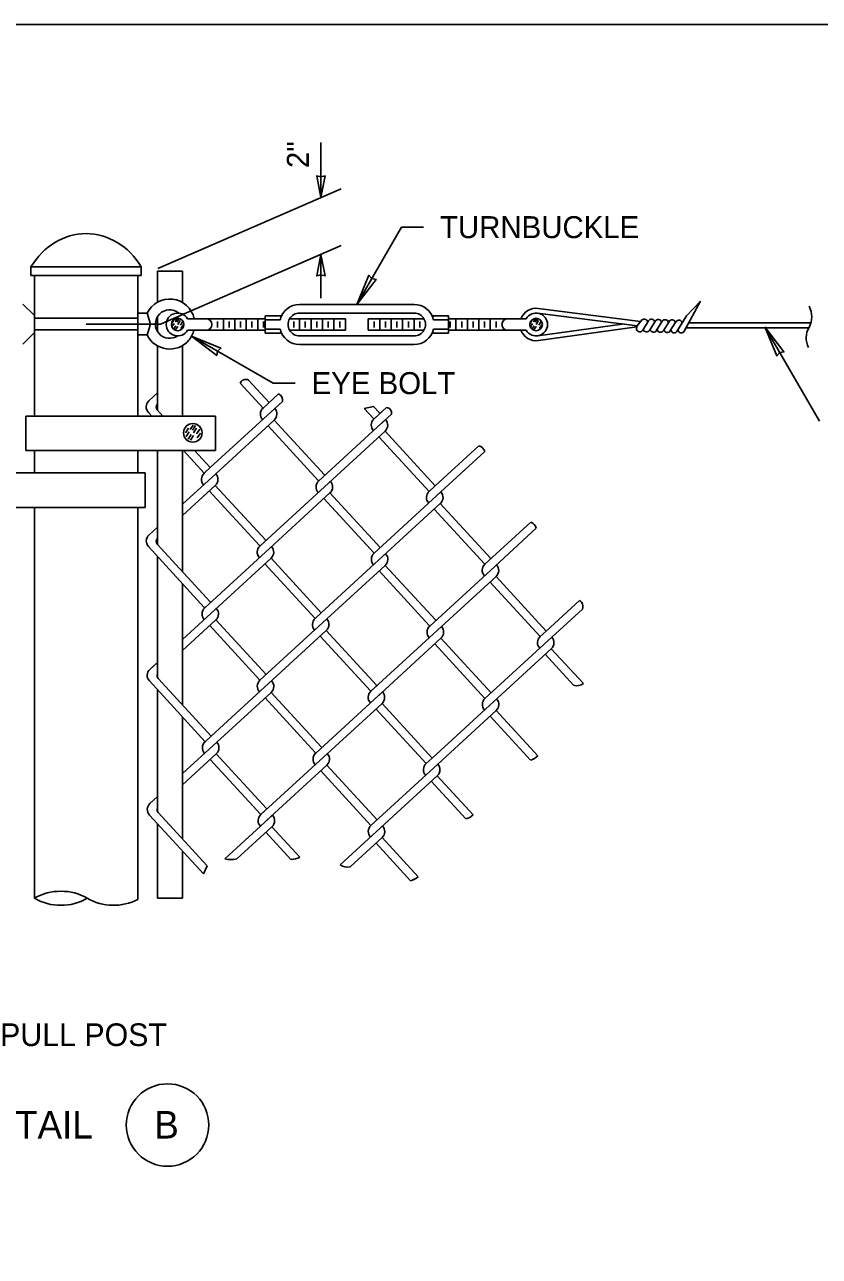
# Model space of a CAD drawing. Extents: x 99862 to 104211, y 98939 to 105076.
# Drawn here: x 101919 to 102497, y 104179 to 105076 of the extents above; entities that cross this region are included whole.
import ezdxf

# ---------------------------------------------------------------- set-up
doc = ezdxf.new("R2010")
doc.units = 0
for name, color, linetype in [('Level 1', 7, 'Continuous'), ('Level 15', 7, 'Continuous'), ('Level 2', 7, 'Continuous'), ('Level 20', 7, 'Continuous'), ('Level 4', 7, 'Continuous'), ('Level 7', 7, 'Continuous'), ('Level 9', 7, 'Continuous')]:
    doc.layers.add(name, color=color, linetype=linetype)

msp = doc.modelspace()

# ---------------------------------------------------------------- linework, layer by layer
at = {"layer": 'Level 1'}
msp.add_lwpolyline([(99862, 102999.5), (103151, 102999.5), (103151, 105075.5), (99862, 105075.5)], close=True, dxfattribs=at)
at = {"layer": 'Level 15'}
for p, q in [((102134.53, 104949.58), (102134.53, 104989.71)), ((102015.79, 104897.93), (102149.21, 104955.96)), ((102134.53, 104949.58), (102134.53, 104949.58)), ((102160.66, 104871.75), (102193.16, 104928.04)), ((102193.16, 104928.04), (102209.16, 104928.04)), ((102134.54, 104908.22), (102134.54, 104876.22)), ((102457.47, 104855.52), (102497.22, 104786.68)), ((102040.49, 104848.67), (102099.74, 104814.46)), ((102099.74, 104814.46), (102115.74, 104814.46))]:
    msp.add_line(p, q, dxfattribs=at)
for points in [[(102134.53, 104949.58), (102137.62, 104965.31), (102134.53, 104964.58), (102131.45, 104965.31)], [(102134.54, 104908.22), (102137.62, 104892.49), (102134.54, 104893.22), (102131.45, 104892.49)], [(102160.66, 104871.75), (102174.66, 104890.03), (102171.55, 104890.61), (102169.49, 104893.01)], [(102457.47, 104855.52), (102466.3, 104834.25), (102468.36, 104836.66), (102471.47, 104837.24)], [(102040.49, 104848.67), (102061.76, 104839.84), (102059.35, 104837.78), (102058.77, 104834.67)]]:
    msp.add_lwpolyline(points, close=True, dxfattribs=at)
msp.add_lwpolyline([(101963.72, 104857.47), (102017.83, 104857.47), (102149.21, 104914.6)], dxfattribs=at)
at = {"layer": 'Level 2'}
for p, q in [((101917.63, 104872.08), (101926.05, 104863.66)), ((102119.01, 104871.75), (102202.32, 104871.75)), ((102398.97, 104852.3), (102410.82, 104874.17)), ((102400.6, 104863.41), (102410.82, 104874.17)), ((102008.04, 104865.29), (102010.45, 104857.48)), ((102094.01, 104863.42), (102094.01, 104850.92)), ((102105.83, 104863.42), (102094.01, 104863.42)), ((102119.01, 104865.5), (102202.32, 104865.5)), ((102215.49, 104863.42), (102227.31, 104863.42)), ((102227.31, 104863.42), (102227.31, 104850.92)), ((102292.19, 104865.43), (102364.74, 104856.08)), ((102292.64, 104868.91), (102367.01, 104859.31)), ((102393.57, 104852.15), (102400.6, 104863.41)), ((101926.05, 104861.65), (101926.05, 104853.31)), ((101926.05, 104861.65), (102001.39, 104861.65)), ((101926.05, 104857.48), (101926.05, 104853.31)), ((102008.04, 104849.67), (102010.45, 104857.48)), ((102025.77, 104857.64), (102027.29, 104859.98)), ((102026.12, 104855.36), (102027.8, 104857.94)), ((102027.3, 104853.73), (102028.91, 104856.22)), ((102028.42, 104859.21), (102030.07, 104861.75)), ((102028.55, 104852.95), (102030.34, 104855.71)), ((102029.74, 104858.9), (102031.49, 104861.6)), ((102030.33, 104857.17), (102032.15, 104859.97)), ((102032.28, 104856.57), (102034.1, 104859.37)), ((102032.69, 104854.23), (102034.51, 104857.03)), ((102051.06, 104861.34), (102037.55, 104861.34)), ((102094.01, 104861.34), (102051.06, 104861.34)), ((102059.4, 104859.25), (102059.4, 104855.09)), ((102063.56, 104861.34), (102063.56, 104853.01)), ((102067.73, 104859.25), (102067.73, 104855.09)), ((102071.89, 104861.34), (102071.89, 104853.01)), ((102076.06, 104859.25), (102076.06, 104855.09)), ((102080.22, 104861.34), (102080.22, 104853.01)), ((102084.39, 104859.25), (102084.39, 104855.09)), ((102088.55, 104861.34), (102088.55, 104853.01)), ((102092.72, 104859.25), (102092.72, 104855.09)), ((102111.83, 104861.34), (102152.35, 104861.34)), ((102114.86, 104859.25), (102114.86, 104855.09)), ((102119.03, 104861.34), (102119.03, 104853.01)), ((102123.19, 104859.25), (102123.19, 104855.09)), ((102127.36, 104861.34), (102127.36, 104853.01)), ((102131.52, 104859.25), (102131.52, 104855.09)), ((102135.69, 104861.34), (102135.69, 104853.01)), ((102139.85, 104859.25), (102139.85, 104855.09)), ((102144.02, 104861.34), (102144.02, 104853.01)), ((102148.19, 104859.25), (102148.19, 104855.09)), ((102152.35, 104861.34), (102152.35, 104853.01)), ((102169.01, 104861.34), (102169.01, 104853.01)), ((102209.53, 104861.34), (102169.01, 104861.34)), ((102173.18, 104859.25), (102173.18, 104855.09)), ((102177.34, 104861.34), (102177.34, 104853.01)), ((102181.51, 104859.25), (102181.51, 104855.09)), ((102185.68, 104861.34), (102185.68, 104853.01)), ((102189.84, 104859.25), (102189.84, 104855.09)), ((102194.01, 104861.34), (102194.01, 104853.01)), ((102198.17, 104859.25), (102198.17, 104855.09)), ((102202.34, 104861.34), (102202.34, 104853.01)), ((102206.5, 104859.25), (102206.5, 104855.09)), ((102227.31, 104861.34), (102270.4, 104861.34)), ((102228.64, 104859.25), (102228.64, 104855.09)), ((102232.81, 104861.34), (102232.81, 104853.01)), ((102236.98, 104859.25), (102236.98, 104855.09)), ((102241.14, 104861.34), (102241.14, 104853.01)), ((102245.31, 104859.25), (102245.31, 104855.09)), ((102249.47, 104861.34), (102249.47, 104853.01)), ((102253.64, 104859.25), (102253.64, 104855.09)), ((102257.8, 104861.34), (102257.8, 104853.01)), ((102261.97, 104859.25), (102261.97, 104855.09)), ((102270.4, 104861.34), (102283.91, 104861.34)), ((102286.57, 104857.64), (102288.09, 104859.98)), ((102286.92, 104855.36), (102288.6, 104857.94)), ((102288.1, 104853.73), (102289.71, 104856.22)), ((102289.22, 104859.21), (102290.86, 104861.75)), ((102289.34, 104852.95), (102291.13, 104855.71)), ((102290.54, 104858.9), (102292.29, 104861.6)), ((102291.13, 104857.17), (102292.94, 104859.97)), ((102292.28, 104848.92), (102353.69, 104857.5)), ((102292.77, 104845.45), (102364.3, 104855.45)), ((102293.08, 104856.57), (102294.9, 104859.37)), ((102293.48, 104854.23), (102295.3, 104857.03)), ((102364.74, 104856.08), (102367.54, 104859.82)), ((102368.66, 104853), (102372.86, 104859.8)), ((102373.61, 104852.78), (102377.93, 104859.74)), ((102378.53, 104852.54), (102382.93, 104859.52)), ((102383.48, 104852.32), (102388.15, 104859.65)), ((102388.51, 104852.22), (102392.91, 104859.17)), ((102400.33, 104854.82), (102489.54, 104854.82)), ((102402.23, 104858.32), (102491.09, 104858.32)), ((101917.63, 104842.88), (101926.05, 104851.3)), ((101926.05, 104853.31), (102001.39, 104853.31)), ((102051.06, 104853.01), (102037.55, 104853.01)), ((102094.01, 104853.01), (102051.06, 104853.01)), ((102105.83, 104850.92), (102094.01, 104850.92)), ((102111.83, 104853.01), (102152.35, 104853.01)), ((102119, 104848.84), (102202.38, 104848.84)), ((102209.53, 104853.01), (102169.01, 104853.01)), ((102215.49, 104850.92), (102227.31, 104850.92)), ((102227.31, 104853.01), (102270.4, 104853.01)), ((102270.4, 104853.01), (102283.91, 104853.01)), ((102119, 104842.59), (102202.4, 104842.59))]:
    msp.add_line(p, q, dxfattribs=at)
for points in [[(101926.05, 104861.65), (101926.05, 104863.66)], [(102001.39, 104862.69), (102001.39, 104865.29), (102008.04, 104865.29)], [(102104.83, 104860.58), (102094.01, 104860.58)], [(102104.83, 104853.76), (102094.01, 104853.76)], [(102216.49, 104860.58), (102227.31, 104860.58)], [(102216.49, 104853.76), (102227.31, 104853.76)], [(101926.05, 104853.31), (101926.05, 104851.3)], [(102001.39, 104852.28), (102001.39, 104849.67), (102008.04, 104849.67)]]:
    msp.add_lwpolyline(points, dxfattribs=at)
for centre, radius in [((102030.33, 104857.17), 4.58), ((102291.13, 104857.17), 4.58), ((102041.31, 104778.25), 6.76)]:
    msp.add_circle(centre, radius, dxfattribs=at)
for centre, radius, start, end in [((102024.5, 104857.48), 18.22, 12.20835, 154.62307), ((102119, 104857.17), 14.58, 89.9981, 166.47525), ((102202.32, 104857.17), 14.58, 13.52807, 90.0019), ((102024.5, 104857.48), 10.41, 49.96946, 221.94815), ((102030.33, 104857.17), 8.33, 30, 330), ((102119, 104857.17), 8.33, 89.99821, 210), ((102202.32, 104857.17), 8.33, 329.99866, 90.00179), ((102291.13, 104857.17), 11.83, 82.64945, 159.385), ((102291.13, 104857.17), 8.33, 210, 150), ((102476.4, 104862.76), 15.35, 330, 30), ((102051.06, 104857.17), 4.17, 270, 90), ((102119, 104857.17), 14.58, 193.52475, 270), ((102202.32, 104857.17), 14.58, 270, 346.47623), ((102270.4, 104857.17), 4.17, 90, 270), ((102366.57, 104854.38), 2.5, 137.27331, 330.15706), ((102369.74, 104858.63), 2.5, 3.58666, 151.53493), ((102371.57, 104854.23), 2.5, 191.22024, 331.82535), ((102374.99, 104858.48), 2.5, 11.16264, 148.28981), ((102376.57, 104854.09), 2.5, 191.16264, 333.88098), ((102380, 104858.33), 2.5, 10.08945, 150.54633), ((102385.06, 104858.18), 2.5, 10.9904, 147.78546), ((102390.06, 104858.03), 2.5, 11.61323, 155.14251), ((102395.03, 104857.83), 2.5, 13.01144, 147.67573), ((102502.99, 104847.41), 15.35, 150, 206.99342), ((102024.5, 104857.48), 18.22, 205.37693, 319.9883), ((102024.5, 104857.48), 10.41, 221.94815, 303.90844), ((102024.5, 104857.48), 18.22, 319.9883, 345.77824), ((102119, 104857.17), 8.33, 210, 270), ((102202.32, 104857.17), 8.33, 270, 329.99866), ((102291.13, 104857.17), 11.83, 200.615, 277.95607), ((102381.57, 104853.94), 2.5, 191.03065, 335.14251), ((102386.57, 104853.79), 2.5, 190.91097, 334.35076), ((102391.56, 104853.64), 2.5, 190.98978, 332.61253), ((102396.77, 104853.49), 2.5, 184.71631, 331.55502)]:
    msp.add_arc(centre, radius, start, end, dxfattribs=at)
at = {"layer": 'Level 4'}
for p, q in [((102075.88, 104814.37), (102092.41, 104796.35)), ((102081.94, 104816.64), (102096.83, 104800.41)), ((102015.61, 104807.3), (102009.35, 104801.55)), ((102106.56, 104801.2), (102053.98, 104752.93)), ((102103.76, 104806.77), (102092.41, 104796.35)), ((102008.99, 104793.08), (102011.42, 104790.43)), ((102015.44, 104794.92), (102019.56, 104790.43)), ((102172.84, 104797.47), (102166.01, 104796.03)), ((102166.01, 104796.03), (102172.77, 104788.67)), ((102172.84, 104797.47), (102177.19, 104792.73)), ((102182.37, 104796.8), (102173.11, 104788.3)), ((102177.53, 104792.36), (102173.11, 104788.3)), ((102185.85, 104791.85), (102177.16, 104783.88)), ((102177.19, 104792.73), (102177.53, 104792.36)), ((102100.53, 104787.51), (102058.04, 104748.51)), ((102092.05, 104787.88), (102092.05, 104787.88)), ((102096.11, 104783.46), (102132.63, 104743.68)), ((102100.53, 104787.51), (102137.05, 104747.73)), ((102181.59, 104787.94), (102132.96, 104743.31)), ((102172.77, 104788.67), (102173.11, 104788.3)), ((102181.22, 104779.46), (102090.11, 104695.83)), ((102172.74, 104779.82), (102172.74, 104779.82)), ((102176.8, 104775.4), (102213.32, 104735.62)), ((102181.22, 104779.46), (102217.74, 104739.68)), ((102034.44, 104765.35), (102049.56, 104748.88)), ((102042.58, 104765.35), (102053.98, 104752.93)), ((102249.53, 104768.86), (102217.74, 104739.68)), ((102253.91, 104764.73), (102221.8, 104735.26)), ((102058.04, 104748.51), (102033.8, 104726.26)), ((102053.98, 104752.93), (102049.56, 104748.87)), ((102137.05, 104747.73), (102137.38, 104747.36)), ((102057.68, 104740.03), (102033.8, 104718.11)), ((102049.2, 104740.4), (102049.2, 104740.4)), ((102057.68, 104740.03), (102094.19, 104700.25)), ((102132.63, 104743.68), (102132.96, 104743.31)), ((102217.74, 104739.68), (102213.32, 104735.62)), ((102053.26, 104735.98), (102089.77, 104696.2)), ((102141.08, 104734.47), (102094.17, 104691.41)), ((102132.6, 104734.83), (102132.6, 104734.83)), ((102136.66, 104730.41), (102173.17, 104690.63)), ((102141.08, 104734.47), (102177.59, 104694.69)), ((102221.8, 104735.26), (102173.17, 104690.63)), ((102221.43, 104726.78), (102134.74, 104647.21)), ((102212.96, 104727.14), (102212.96, 104727.14)), ((102217.01, 104722.72), (102253.53, 104682.94)), ((102221.43, 104726.78), (102257.95, 104687)), ((102287.31, 104713.28), (102253.87, 104682.57)), ((102015.61, 104709.57), (102009.42, 104703.88)), ((102291.27, 104708.76), (102257.92, 104678.15)), ((102009.05, 104695.4), (102049.63, 104651.2)), ((102015.5, 104697.25), (102054.05, 104655.26)), ((102089.77, 104696.2), (102090.11, 104695.83)), ((102094.19, 104700.25), (102094.53, 104699.88)), ((102094.53, 104699.88), (102094.53, 104699.88)), ((102098.23, 104686.99), (102033.8, 104627.85)), ((102094.17, 104691.41), (102049.97, 104650.83)), ((102089.75, 104687.35), (102089.75, 104687.35)), ((102098.23, 104686.99), (102134.74, 104647.21)), ((102257.95, 104687), (102258.29, 104686.63)), ((102258.29, 104686.63), (102258.29, 104686.63)), ((102093.81, 104682.93), (102130.32, 104643.15)), ((102181.29, 104681.79), (102138.8, 104642.79)), ((102172.81, 104682.15), (102172.81, 104682.15)), ((102176.87, 104677.73), (102213.39, 104637.95)), ((102181.29, 104681.79), (102217.81, 104642.01)), ((102257.92, 104678.15), (102213.72, 104637.58)), ((102253.53, 104682.94), (102253.87, 104682.57)), ((102261.98, 104673.73), (102170.87, 104590.1)), ((102253.5, 104674.1), (102253.5, 104674.1)), ((102257.56, 104669.68), (102294.08, 104629.9)), ((102261.98, 104673.73), (102298.5, 104633.95)), ((102049.63, 104651.2), (102049.97, 104650.83)), ((102054.05, 104655.26), (102054.39, 104654.89)), ((102322.62, 104656.1), (102298.5, 104633.95)), ((102324.76, 104649.92), (102302.56, 104629.53)), ((102058.08, 104641.99), (102033.8, 104619.7)), ((102049.6, 104642.36), (102049.6, 104642.36)), ((102058.08, 104641.99), (102094.6, 104602.21)), ((102138.8, 104642.79), (102090.18, 104598.15)), ((102134.74, 104647.21), (102130.32, 104643.15)), ((102217.81, 104642.01), (102218.14, 104641.64)), ((102053.66, 104637.94), (102090.18, 104598.15)), ((102138.44, 104634.31), (102054.69, 104557.44)), ((102129.96, 104634.67), (102129.96, 104634.67)), ((102134.02, 104630.25), (102170.53, 104590.47)), ((102138.44, 104634.31), (102174.95, 104594.53)), ((102213.39, 104637.95), (102213.72, 104637.58)), ((102302.56, 104629.53), (102253.93, 104584.9)), ((102298.5, 104633.95), (102294.08, 104629.9)), ((102221.84, 104628.74), (102174.93, 104585.68)), ((102213.36, 104629.1), (102213.36, 104629.1)), ((102302.19, 104621.06), (102215.5, 104541.48)), ((102217.42, 104624.68), (102253.93, 104584.9)), ((102221.84, 104628.74), (102258.35, 104588.96)), ((102293.72, 104621.42), (102293.72, 104621.42)), ((102302.19, 104621.06), (102325.52, 104595.64)), ((102297.77, 104617), (102318.4, 104594.52)), ((102015.61, 104611.15), (102010.06, 104606.06)), ((102014.48, 104610.12), (102010.06, 104606.06)), ((102009.7, 104597.58), (102050.27, 104553.38)), ((102016.15, 104599.43), (102054.69, 104557.44)), ((102175.29, 104594.16), (102170.87, 104590.1)), ((102174.95, 104594.53), (102175.29, 104594.16)), ((102098.29, 104589.31), (102058.75, 104553.02)), ((102089.81, 104589.68), (102089.81, 104589.68)), ((102093.87, 104585.26), (102130.39, 104545.48)), ((102098.29, 104589.31), (102134.81, 104549.53)), ((102179.35, 104589.74), (102130.73, 104545.11)), ((102170.53, 104590.47), (102170.87, 104590.1)), ((102178.99, 104581.26), (102090.82, 104500.33)), ((102170.51, 104581.62), (102170.51, 104581.62)), ((102174.57, 104577.2), (102211.08, 104537.42)), ((102178.99, 104581.26), (102215.5, 104541.48)), ((102262.05, 104576.06), (102219.56, 104537.06)), ((102253.57, 104576.42), (102253.57, 104576.42)), ((102262.05, 104576.06), (102292.29, 104543.11)), ((102257.63, 104572), (102287.16, 104539.83)), ((102058.75, 104553.02), (102033.8, 104530.11)), ((102054.69, 104557.44), (102050.27, 104553.38)), ((102134.81, 104549.53), (102135.15, 104549.16)), ((102058.39, 104544.54), (102033.8, 104521.97)), ((102049.91, 104544.9), (102049.91, 104544.9)), ((102053.97, 104540.48), (102090.48, 104500.7)), ((102058.39, 104544.54), (102094.9, 104504.76)), ((102130.39, 104545.48), (102130.73, 104545.11)), ((102215.5, 104541.48), (102211.08, 104537.42)), ((102138.84, 104536.27), (102094.88, 104495.91)), ((102130.36, 104536.63), (102130.36, 104536.63)), ((102134.42, 104532.21), (102170.94, 104492.43)), ((102138.84, 104536.27), (102175.36, 104496.49)), ((102219.56, 104537.06), (102170.94, 104492.43)), ((102219.2, 104528.58), (102148.45, 104463.65)), ((102210.72, 104528.94), (102210.72, 104528.94)), ((102214.78, 104524.52), (102239.89, 104497.17)), ((102219.2, 104528.58), (102245.42, 104500.02)), ((102015.61, 104513.42), (102010.13, 104508.39)), ((102095.24, 104504.39), (102090.82, 104500.33)), ((102094.9, 104504.76), (102095.24, 104504.39)), ((102009.76, 104499.91), (102009.76, 104499.91)), ((102009.76, 104499.91), (102049.06, 104457.1)), ((102016.21, 104501.76), (102051.77, 104463.02)), ((102099.3, 104499.97), (102064.58, 104468.1)), ((102090.48, 104500.7), (102090.82, 104500.33)), ((102098.94, 104491.49), (102073.46, 104468.11)), ((102090.46, 104491.85), (102090.46, 104491.85)), ((102094.52, 104487.43), (102112.77, 104467.54)), ((102098.94, 104491.49), (102119.27, 104469.34)), ((102179.05, 104483.59), (102155.75, 104462.2)), ((102170.57, 104483.95), (102170.57, 104483.95)), ((102174.63, 104479.53), (102199.74, 104452.18)), ((102179.05, 104483.59), (102205.27, 104455.02)), ((102051.77, 104463.02), (102049.06, 104457.1))]:
    msp.add_line(p, q, dxfattribs=at)
for centre, radius, start, end in [((102079.8, 104813.13), 4.11, 58.5177, 162.43792), ((102013.41, 104797.13), 6, 132.54951, 222.54951), ((102101.11, 104801.95), 5.5, 352.10576, 61.19252), ((102017.65, 104796.95), 3, 132.54951, 222.54951), ((102096.47, 104791.93), 6, 132.54951, 222.54951), ((102096.47, 104791.93), 6, 312.54951, 42.54951), ((102181.83, 104792.72), 4.11, 347.74483, 82.53062), ((102177.16, 104783.88), 6, 132.54951, 222.54951), ((102177.16, 104783.88), 6, 312.54951, 42.54951), ((102247.6, 104762.44), 6.71, 20.00564, 73.27685), ((102053.62, 104744.45), 6, 132.54951, 222.54951), ((102053.62, 104744.45), 6, 312.54951, 42.54951), ((102137.02, 104738.89), 6, 132.54951, 222.54951), ((102137.02, 104738.89), 6, 312.54951, 42.54951), ((102217.38, 104731.2), 6, 132.54951, 222.54951), ((102217.38, 104731.2), 6, 312.54951, 42.54951), ((102284.78, 104707.07), 6.71, 14.62705, 67.76777), ((102013.48, 104699.46), 6, 132.54951, 222.54951), ((102017.71, 104699.28), 3, 134.49043, 222.54951), ((102094.17, 104691.41), 6, 132.54951, 222.54951), ((102094.17, 104691.41), 6, 312.54951, 42.54951), ((102177.23, 104686.21), 6, 132.54951, 222.54951), ((102177.23, 104686.21), 6, 312.54951, 42.54951), ((102257.92, 104678.15), 6, 132.54951, 222.54951), ((102257.92, 104678.15), 6, 312.54951, 42.54951), ((102054.02, 104646.41), 6, 132.54951, 222.54951), ((102054.02, 104646.41), 6, 312.54951, 42.54951), ((102320.65, 104651.95), 4.59, 333.67438, 64.53615), ((102134.38, 104638.73), 6, 132.54951, 222.54951), ((102134.38, 104638.73), 6, 312.54951, 42.54951), ((102217.78, 104633.16), 6, 132.54951, 222.54951), ((102217.78, 104633.16), 6, 312.54951, 42.54951), ((102298.14, 104625.48), 6, 132.54951, 222.54951), ((102298.14, 104625.48), 6, 312.54951, 42.54951), ((102014.12, 104601.64), 6, 132.54951, 222.54951), ((102018.36, 104601.46), 3, 156.23134, 222.54951), ((102094.23, 104593.73), 6, 132.54951, 222.54951), ((102094.23, 104593.73), 6, 312.54951, 42.54951), ((102320.91, 104601.78), 7.68, 250.92994, 306.90034), ((102174.93, 104585.68), 6, 132.54951, 222.54951), ((102174.93, 104585.68), 6, 312.54951, 42.54951), ((102257.99, 104580.48), 6, 132.54951, 222.54951), ((102257.99, 104580.48), 6, 312.54951, 42.54951), ((102054.33, 104548.96), 6, 132.54951, 222.54951), ((102054.33, 104548.96), 6, 312.54951, 42.54951), ((102134.78, 104540.69), 6, 132.54951, 222.54951), ((102134.78, 104540.69), 6, 312.54951, 42.54951), ((102280.31, 104556.17), 17.72, 292.76039, 312.54951), ((102215.14, 104533), 6, 132.54951, 222.54951), ((102215.14, 104533), 6, 312.54951, 42.54951), ((102014.18, 104503.97), 6, 132.54951, 222.54951), ((102018.42, 104503.78), 3, 159.61537, 222.54951), ((102094.88, 104495.91), 6, 132.54951, 222.54951), ((102094.88, 104495.91), 6, 312.54951, 42.54951), ((102237.45, 104508.69), 11.77, 281.91503, 312.54951), ((102174.99, 104488.01), 6, 132.54951, 222.54951), ((102174.99, 104488.01), 6, 312.54951, 42.54951), ((102069.01, 104484.28), 16.77, 254.69318, 285.39252), ((102111.64, 104484.28), 16.77, 273.86972, 297.04869), ((102154.28, 104473.88), 11.77, 240.36921, 277.19447), ((102197.31, 104463.7), 11.77, 281.91503, 312.54951)]:
    msp.add_arc(centre, radius, start, end, dxfattribs=at)
at = {"layer": 'Level 7'}
for p, q in [((101923.55, 104899.07), (102003.8, 104899.07)), ((101923.55, 104892.8), (101923.55, 104899.07)), ((102003.8, 104892.8), (102003.8, 104899.07)), ((102003.8, 104892.8), (101923.55, 104892.8)), ((101926.12, 104790.43), (101926.12, 104892.8)), ((102001.35, 104790.43), (102001.35, 104892.8)), ((102015.61, 104895.93), (102033.8, 104895.93)), ((102033.8, 104873.16), (102033.8, 104895.93)), ((102033.8, 104790.43), (102033.8, 104841.81)), ((101919.85, 104765.35), (101919.85, 104790.43)), ((102057.77, 104790.43), (101919.85, 104790.43)), ((102039.45, 104780.64), (102041.61, 104783.97)), ((102041.05, 104780.27), (102043.25, 104783.66)), ((102057.77, 104765.35), (102057.77, 104790.43)), ((102035.89, 104778.18), (102038.08, 104781.57)), ((102036.5, 104775.71), (102038.7, 104779.11)), ((102037.87, 104773.66), (102040.05, 104777.02)), ((102039.57, 104773.01), (102041.77, 104776.4)), ((102041.77, 104778.17), (102043.96, 104781.56)), ((102044.12, 104777.44), (102046.33, 104780.83)), ((102044.61, 104774.61), (102046.82, 104778.01)), ((102016.37, 104765.35), (101919.85, 104765.35)), ((101926.12, 104749.09), (101926.12, 104765.35)), ((102001.35, 104749.09), (102001.35, 104765.35)), ((102051.51, 104765.35), (102014.54, 104765.35)), ((102033.8, 104677.32), (102033.8, 104765.35)), ((102057.77, 104765.35), (102051.51, 104765.35)), ((101868.71, 104749.09), (102006.64, 104749.09)), ((102006.64, 104724.02), (102006.64, 104749.09)), ((101910.12, 104724.02), (102006.64, 104724.02)), ((101926.12, 104439.37), (101926.12, 104724.02)), ((102001.35, 104438.52), (102001.35, 104724.02)), ((102033.8, 104580.2), (102033.8, 104668.45)), ((102033.8, 104482.6), (102033.8, 104571.33)), ((102033.8, 104439.37), (102033.8, 104473.73)), ((102033.8, 104439.37), (102015.61, 104439.37))]:
    msp.add_line(p, q, dxfattribs=at)
for points in [[(102015.79, 104895.93), (102015.61, 104895.93), (102015.61, 104873.39)], [(102015.61, 104862.9), (102015.61, 104852.06)], [(102015.61, 104841.57), (102015.61, 104810.73)], [(102015.61, 104810.73), (102015.61, 104794.73)], [(102015.61, 104765.35), (102015.61, 104697.13)], [(102015.61, 104688.26), (102015.61, 104600.25)], [(102015.61, 104591.14), (102015.61, 104502.74)], [(102015.61, 104493.54), (102015.61, 104439.37)]]:
    msp.add_lwpolyline(points, dxfattribs=at)
for centre, start, end in [((101945.31, 104406.12), 60, 120), ((101945.31, 104472.61), 240, 300), ((101983.7, 104472.61), 240, 297.38354)]:
    msp.add_arc(centre, 38.38, start, end, dxfattribs=at)
msp.add_ellipse((101963.68, 104867.34), major_axis=(0, 55.98), ratio=0.870041, start_param=5.315025, end_param=7.251346, dxfattribs=at)
at = {"layer": 'Level 9'}
msp.add_circle((102022.95, 104274.26), 30, dxfattribs=at)

# ---------------------------------------------------------------- texts
at = {"layer": 'Level 20'}
msp.add_text('2"', height=16, rotation=89.99424, dxfattribs=at).set_placement((102125.77, 104971.07))
for s, height, p in [('TURNBUCKLE', 16, (102221.16, 104920.04)), ('EYE BOLT', 16, (102127.74, 104806.46)), ('PULL POST', 16.5, (101901.1, 104331.77)), ('DETAIL', 20, (101874.88, 104264.44)), ('B', 20, (102013.31, 104264.44))]:
    msp.add_text(s, height=height, dxfattribs=at).set_placement(p)

doc.saveas('drawing.dxf')
